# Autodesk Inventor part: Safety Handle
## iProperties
Shininess: 77.0
Length Units: 11269
Angle Units: 11279
Time Units: 11290
Mass Units: 11283
Length Display Precision: 3
Angle Display Precision: 2
Created: 2002-02
Part Number: Safety Handle
Document SubType Name: Modeling
Designer: ***
Density: 1 g/cm^3
Density: 0.0
Volumn: 0.0
Area: 0.0
PropertySet Name: Model Information
Control State: 0
Master: False
Checked Out: False
Author: ***
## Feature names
1. Revolution1
2. Extrusion1
